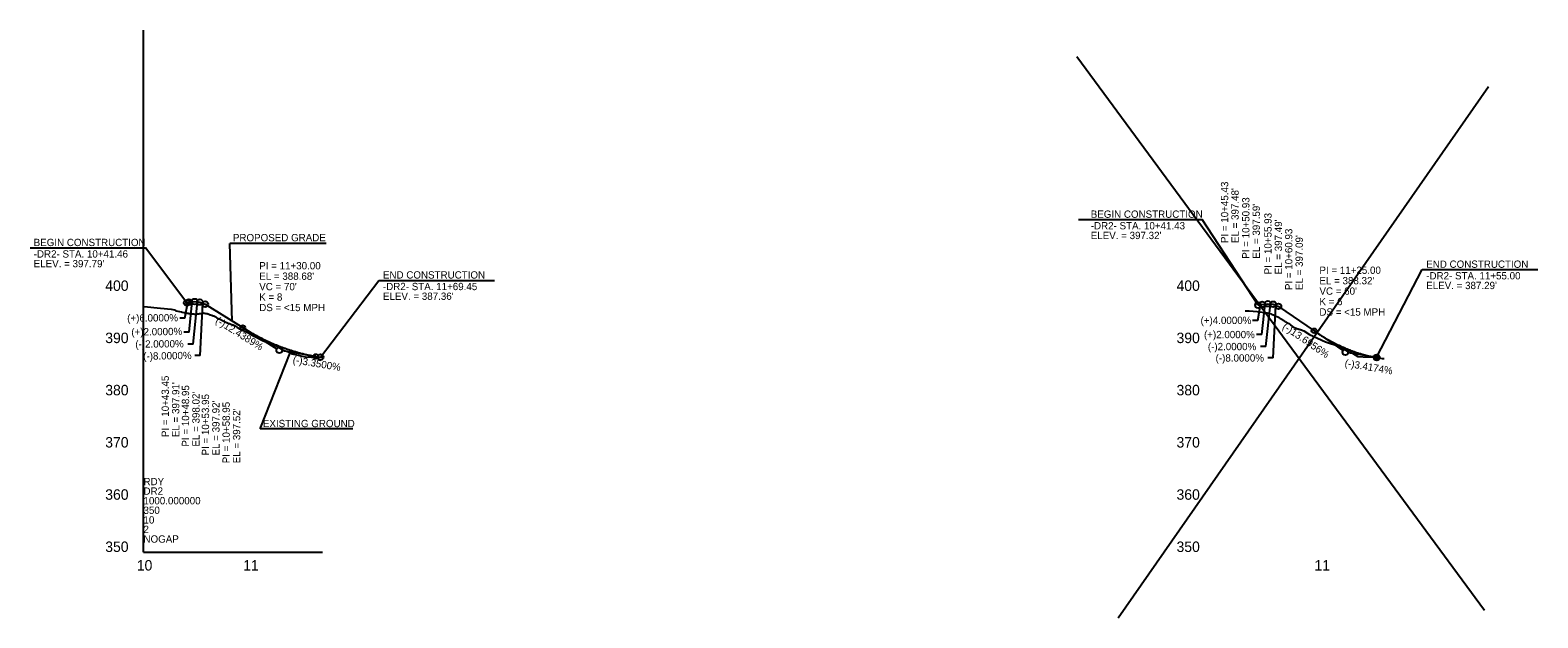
# Model space of a CAD drawing. Extents: x 1625686 to 1640492, y 1161393 to 1175642.
# Drawn here: x 1630096 to 1631539, y 1165841 to 1166403 of the extents above; entities that cross this region are included whole.
import ezdxf

# ---------------------------------------------------------------- set-up
doc = ezdxf.new("R2010")
doc.units = 0
for name, color, linetype in [('Exist Profile Cell', 7, 'Continuous'), ('Exist Vertical Profile Ground Line', 7, 'Continuous'), ('Exist Vertical Profile Horizontal Axis Label Major', 7, 'Continuous'), ('Exist Vertical Profile Vertical Axis Label', 7, 'Continuous'), ('Prop Vertical Profile Curve Label', 7, 'Continuous'), ('Prop Vertical Profile Grade', 7, 'Continuous'), ('Prop Vertical Profile Grade Label', 7, 'Continuous'), ('Prop VPI Label', 7, 'Continuous'), ('Scratch_Level_3', 7, 'Continuous')]:
    doc.layers.add(name, color=color, linetype=linetype)

msp = doc.modelspace()

# ---------------------------------------------------------------- linework, layer by layer
at = {"layer": 'Exist Profile Cell'}
for q in [(1630204.3, 1166403.4), (1630375.7, 1165903.4), (1630204.3, 1165903.4)]:
    msp.add_line((1630204.3, 1165903.4), q, dxfattribs=at)
at = {"layer": 'Exist Vertical Profile Ground Line'}
for points in [[(1630204.3, 1166138.9), (1630205, 1166138.9), (1630220.6, 1166137.2), (1630230.7, 1166136.2), (1630232.4, 1166135.8), (1630234.1, 1166135.5), (1630235.1, 1166134.5), (1630240.7, 1166133.6), (1630241.3, 1166133.3), (1630242.9, 1166133), (1630243.5, 1166132.9), (1630244.1, 1166132.8), (1630244.7, 1166132.7), (1630245.3, 1166132.6), (1630245.9, 1166132.5), (1630246.5, 1166132.4), (1630247.1, 1166132.3), (1630247.7, 1166132.2), (1630248.3, 1166132.1), (1630248.9, 1166132), (1630249.5, 1166132), (1630250.3, 1166131.9), (1630250.7, 1166131.8), (1630251.3, 1166131.7), (1630251.9, 1166131.7), (1630252.5, 1166131.6), (1630253.1, 1166131.5), (1630254, 1166131.5), (1630254.3, 1166131.5), (1630254.9, 1166131.5), (1630255.5, 1166131.6), (1630256.1, 1166131.6), (1630256.6, 1166131.7), (1630257.3, 1166131.8), (1630257.9, 1166131.9), (1630258.5, 1166132), (1630259.1, 1166132.1), (1630259.6, 1166132.2), (1630260.2, 1166132.3), (1630260.8, 1166132.4), (1630261.5, 1166132.6), (1630262, 1166132.5), (1630262.6, 1166132.4), (1630263.2, 1166132.3), (1630263.8, 1166132.2), (1630264.4, 1166132.1), (1630265.2, 1166132), (1630265.6, 1166131.8), (1630266.2, 1166131.6), (1630266.8, 1166131.4), (1630267.4, 1166131.2), (1630268, 1166130.9), (1630268.6, 1166130.7), (1630269.2, 1166130.5), (1630269.8, 1166130.3), (1630270.4, 1166130.1), (1630271, 1166129.9), (1630271.6, 1166129.7), (1630272.2, 1166129.5), (1630272.8, 1166129.2), (1630273.4, 1166128.8), (1630274, 1166128.4), (1630274.6, 1166128), (1630275.2, 1166127.7), (1630275.8, 1166127.4), (1630276.4, 1166127.1), (1630277, 1166126.8), (1630277.6, 1166126.5), (1630278.2, 1166126.2), (1630278.8, 1166125.9), (1630279.4, 1166125.6), (1630280, 1166125.3), (1630280.6, 1166125), (1630281.2, 1166124.7), (1630281.8, 1166124.4), (1630282.4, 1166124.1), (1630283, 1166123.8), (1630283.6, 1166123.5), (1630284.2, 1166123.3), (1630284.8, 1166123.1), (1630285.4, 1166122.8), (1630286, 1166122.6), (1630286.6, 1166122.4), (1630287.2, 1166122.2), (1630287.8, 1166121.9), (1630288.4, 1166121.7), (1630289, 1166121.5), (1630289.6, 1166121.3), (1630290.2, 1166121.1), (1630290.8, 1166120.9), (1630291.6, 1166120.6), (1630292, 1166120.3), (1630292.6, 1166119.9), (1630293.2, 1166119.5), (1630293.8, 1166119.1), (1630294.4, 1166118.7), (1630295, 1166118.3), (1630295.6, 1166117.8), (1630296.2, 1166117.4), (1630297, 1166116.9), (1630297.4, 1166116.7), (1630298, 1166116.5), (1630298.6, 1166116.2), (1630299.2, 1166116), (1630303.5, 1166114.2), (1630310, 1166110.4), (1630310.8, 1166110.1), (1630318.8, 1166106), (1630331.7, 1166101.1), (1630337.9, 1166097), (1630343, 1166095.4), (1630346.6, 1166093.3), (1630353.5, 1166091.8), (1630359.1, 1166090.6), (1630365.1, 1166090.2), (1630373.8, 1166090.2), (1630375.7, 1166089.9)], [(1631258.9, 1166134.6), (1631262.7, 1166134.7), (1631266.6, 1166134.3), (1631270.2, 1166134), (1631280, 1166132.6), (1631283.6, 1166131.6), (1631284, 1166131.4), (1631284.4, 1166131.2), (1631284.9, 1166131.1), (1631285.3, 1166130.9), (1631285.8, 1166130.7), (1631286.2, 1166130.5), (1631286.6, 1166130.3), (1631287.1, 1166130.1), (1631287.5, 1166129.9), (1631288, 1166129.7), (1631288.4, 1166129.5), (1631288.9, 1166129.3), (1631289.3, 1166129.1), (1631289.8, 1166128.9), (1631290.2, 1166128.7), (1631290.7, 1166128.5), (1631291.2, 1166128.3), (1631291.6, 1166128), (1631292, 1166127.7), (1631292.5, 1166127.4), (1631292.9, 1166127.1), (1631293.3, 1166126.8), (1631293.8, 1166126.5), (1631294.2, 1166126.2), (1631294.7, 1166125.9), (1631295.1, 1166125.6), (1631295.7, 1166125.2), (1631296, 1166125), (1631296.5, 1166124.8), (1631296.9, 1166124.5), (1631297.4, 1166124.3), (1631297.8, 1166124), (1631298.3, 1166123.7), (1631298.7, 1166123.5), (1631299.2, 1166123.2), (1631299.6, 1166123), (1631300.1, 1166122.7), (1631300.5, 1166122.5), (1631301.4, 1166121.9), (1631301.8, 1166121.6), (1631302.3, 1166121.2), (1631302.7, 1166120.8), (1631303.2, 1166120.5), (1631303.6, 1166120.1), (1631304.1, 1166119.8), (1631304.5, 1166119.4), (1631305, 1166119.1), (1631305.9, 1166118.5), (1631306.3, 1166118.3), (1631306.8, 1166118.2), (1631307.2, 1166118.1), (1631307.7, 1166117.9), (1631308.1, 1166117.8), (1631308.5, 1166117.6), (1631309, 1166117.5), (1631309.4, 1166117.4), (1631309.9, 1166117.2), (1631310.3, 1166117.1), (1631310.8, 1166116.9), (1631311.2, 1166116.8), (1631311.7, 1166116.7), (1631312.1, 1166116.5), (1631312.6, 1166116.4), (1631313, 1166116.3), (1631313.5, 1166116.1), (1631313.9, 1166115.9), (1631314.8, 1166115.5), (1631320.5, 1166111.8), (1631335.7, 1166105), (1631349.4, 1166100.3), (1631356.7, 1166096), (1631361.7, 1166094.2), (1631366.8, 1166091), (1631371.8, 1166090.5), (1631383.4, 1166090.1), (1631389.9, 1166089), (1631391.9, 1166088.8)]]:
    msp.add_lwpolyline(points, dxfattribs=at)
at = {"layer": 'Prop Vertical Profile Curve Label'}
for centre in [(1630299.3, 1166118.6), (1631324.7, 1166115.5), (1630369.3, 1166090.9), (1631384.7, 1166089.9)]:
    msp.add_circle(centre, 2.25, dxfattribs=at)
at = {"layer": 'Prop Vertical Profile Grade'}
for p, q in [((1630245.8, 1166142.4), (1630247.8, 1166142.9)), ((1630247.8, 1166142.9), (1630253.3, 1166143.5)), ((1630253.3, 1166143.5), (1630258.3, 1166143)), ((1630258.3, 1166143), (1630263.3, 1166141)), ((1630263.3, 1166141), (1630299.3, 1166118.6)), ((1631271.1, 1166140), (1631275.1, 1166140.8)), ((1631275.1, 1166140.8), (1631280.6, 1166141.4)), ((1631280.6, 1166141.4), (1631285.6, 1166140.9)), ((1631285.6, 1166140.9), (1631290.6, 1166138.9)), ((1631290.6, 1166138.9), (1631324.7, 1166115.5)), ((1630369.3, 1166090.9), (1630373.8, 1166090.2))]:
    msp.add_line(p, q, dxfattribs=at)
for points in [[(1630299.3, 1166118.6), (1630300.7, 1166117.7), (1630302.1, 1166116.9), (1630303.5, 1166116), (1630304.9, 1166115.2), (1630306.3, 1166114.4), (1630307.7, 1166113.6), (1630309.1, 1166112.8), (1630310.5, 1166112), (1630311.9, 1166111.3), (1630313.3, 1166110.5), (1630314.7, 1166109.8), (1630316.1, 1166109), (1630317.5, 1166108.3), (1630318.9, 1166107.6), (1630320.3, 1166106.9), (1630321.7, 1166106.3), (1630323.1, 1166105.6), (1630324.5, 1166105), (1630325.9, 1166104.3), (1630327.3, 1166103.7), (1630328.7, 1166103.1), (1630330.1, 1166102.5), (1630331.5, 1166101.9), (1630332.9, 1166101.3), (1630334.3, 1166100.8), (1630335.7, 1166100.2), (1630337.1, 1166099.7), (1630338.5, 1166099.2), (1630339.9, 1166098.7), (1630341.3, 1166098.2), (1630342.7, 1166097.7), (1630344.1, 1166097.2), (1630345.5, 1166096.8), (1630346.9, 1166096.3), (1630348.3, 1166095.9), (1630349.7, 1166095.5), (1630351.1, 1166095.1), (1630352.5, 1166094.7), (1630353.9, 1166094.3), (1630355.3, 1166093.9), (1630356.7, 1166093.6), (1630358.1, 1166093.2), (1630359.5, 1166092.9), (1630360.9, 1166092.6), (1630362.3, 1166092.3), (1630363.7, 1166092), (1630365.1, 1166091.7), (1630366.5, 1166091.4), (1630367.9, 1166091.2), (1630369.3, 1166090.9)], [(1631324.7, 1166115.5), (1631325.9, 1166114.7), (1631327.1, 1166113.9), (1631328.3, 1166113.1), (1631329.5, 1166112.3), (1631330.7, 1166111.6), (1631331.9, 1166110.8), (1631333.1, 1166110.1), (1631334.3, 1166109.3), (1631335.5, 1166108.6), (1631336.7, 1166107.9), (1631337.9, 1166107.2), (1631339.1, 1166106.5), (1631340.3, 1166105.9), (1631341.5, 1166105.2), (1631342.7, 1166104.6), (1631343.9, 1166104), (1631345.1, 1166103.3), (1631346.3, 1166102.7), (1631347.5, 1166102.1), (1631348.7, 1166101.6), (1631349.9, 1166101), (1631351.1, 1166100.4), (1631352.3, 1166099.9), (1631353.5, 1166099.4), (1631354.7, 1166098.8), (1631355.9, 1166098.3), (1631357.1, 1166097.8), (1631358.3, 1166097.3), (1631359.5, 1166096.9), (1631360.7, 1166096.4), (1631361.9, 1166096), (1631363.1, 1166095.5), (1631364.3, 1166095.1), (1631365.5, 1166094.7), (1631366.7, 1166094.3), (1631367.9, 1166093.9), (1631369.1, 1166093.6), (1631370.3, 1166093.2), (1631371.5, 1166092.9), (1631372.7, 1166092.5), (1631373.9, 1166092.2), (1631375.1, 1166091.9), (1631376.3, 1166091.6), (1631377.5, 1166091.3), (1631378.7, 1166091), (1631379.9, 1166090.8), (1631381.1, 1166090.5), (1631382.3, 1166090.3), (1631383.5, 1166090.1), (1631384.7, 1166089.9)]]:
    msp.add_spline(points, degree=3, dxfattribs=at)
at = {"layer": 'Prop Vertical Profile Grade Label'}
for p, q in [((1631099.2, 1166222), (1631217.8, 1166222)), ((1631271.1, 1166140), (1631217.8, 1166222)), ((1630289.3, 1166124.8), (1630287.1, 1166199)), ((1630379, 1166199), (1630287.1, 1166199)), ((1630095.8, 1166194.9), (1630206.1, 1166194.9)), ((1630245.8, 1166142.4), (1630206.1, 1166194.9)), ((1631384.6, 1166089.9), (1631428.3, 1166174.1)), ((1631428.3, 1166174.1), (1631539, 1166174.1)), ((1630373.8, 1166090.2), (1630429.7, 1166163.8)), ((1630429.7, 1166163.8), (1630540.3, 1166163.8)), ((1630244, 1166127.6), (1630246.8, 1166142.6)), ((1630247.9, 1166114.1), (1630251, 1166143.2)), ((1630251.7, 1166102.6), (1630256.1, 1166143.3)), ((1630258.6, 1166091.7), (1630261.2, 1166141.8)), ((1631270.8, 1166125.5), (1631273.6, 1166140.5)), ((1631274.8, 1166111.9), (1631277.9, 1166141.1)), ((1631278.5, 1166100.4), (1631282.9, 1166141.1)), ((1630244, 1166127.6), (1630239, 1166127.6)), ((1631285.5, 1166089.5), (1631288.1, 1166139.9)), ((1630247.9, 1166114.1), (1630242.9, 1166114.1)), ((1631270.8, 1166125.5), (1631265.8, 1166125.5)), ((1631274.8, 1166111.9), (1631269.8, 1166111.9)), ((1630251.7, 1166102.6), (1630246.7, 1166102.6)), ((1631278.5, 1166100.4), (1631273.5, 1166100.4)), ((1630258.6, 1166091.7), (1630253.6, 1166091.7)), ((1631285.5, 1166089.5), (1631280.5, 1166089.5))]:
    msp.add_line(p, q, dxfattribs=at)
at = {"layer": 'Prop VPI Label'}
for p, q in [((1630299.3, 1166118.6), (1630332, 1166098.3)), ((1631324.7, 1166115.5), (1631352.4, 1166096.5)), ((1630316.1, 1166021.7), (1630344.8, 1166094.4)), ((1630369.3, 1166090.9), (1630337, 1166096.4)), ((1631384.7, 1166089.9), (1631357.4, 1166094.5)), ((1630404.7, 1166021.7), (1630316.1, 1166021.7))]:
    msp.add_line(p, q, dxfattribs=at)
for centre in [(1630245.8, 1166142.4), (1630247.8, 1166142.9), (1630253.3, 1166143.5), (1630258.3, 1166143), (1630263.3, 1166141), (1631271.1, 1166140), (1631275.1, 1166140.8), (1631280.6, 1166141.4), (1631285.6, 1166140.9), (1631290.6, 1166138.9), (1630334.3, 1166096.8), (1631354.7, 1166095), (1630373.8, 1166090.2), (1631384.7, 1166089.9)]:
    msp.add_circle(centre, 2.75, dxfattribs=at)
at = {"layer": 'Scratch_Level_3'}
for p, q in [((1631097.7, 1166378.1), (1631488, 1165847.8)), ((1631137.1, 1165840.6), (1631491.6, 1166349.5))]:
    msp.add_line(p, q, dxfattribs=at)

# ---------------------------------------------------------------- texts
at = {"layer": 'Exist Profile Cell'}
for s, p in [('RDY', (1630204.3, 1165967.6)), ('1000.000000', (1630204.3, 1165949.3)), ('DR2', (1630204.3, 1165958.5)), ('350', (1630204.3, 1165940.1)), ('2', (1630204.3, 1165921.8)), ('10', (1630204.3, 1165930.9)), ('NOGAP', (1630204.3, 1165912.6))]:
    msp.add_text(s, height=7, dxfattribs=at).set_placement(p)
at = {"layer": 'Exist Vertical Profile Horizontal Axis Label Major'}
for s, p in [('10', (1630197.9, 1165885.9)), ('11', (1630299.7, 1165885.9)), ('11', (1631325.1, 1165885.9))]:
    msp.add_text(s, height=10, dxfattribs=at).set_placement(p)
at = {"layer": 'Exist Vertical Profile Vertical Axis Label'}
for s, p in [('400', (1630167.7, 1166153.7)), ('400', (1631193.1, 1166153.7)), ('390', (1630167.7, 1166103.7)), ('390', (1631193.1, 1166103.7)), ('380', (1630167.7, 1166053.7)), ('380', (1631193.1, 1166053.7)), ('370', (1630167.7, 1166003.7)), ('370', (1631193.1, 1166003.7)), ('360', (1630167.7, 1165953.7)), ('360', (1631193.1, 1165953.7)), ('350', (1630167.7, 1165903.7)), ('350', (1631193.1, 1165903.7))]:
    msp.add_text(s, height=10, dxfattribs=at).set_placement(p)
at = {"layer": 'Prop Vertical Profile Curve Label'}
for s, p in [("VC = 70'", (1630315.1, 1166154.3)), ("VC = 60'", (1631329.9, 1166150)), ('K = 8', (1630315.1, 1166144.3)), ('DS = <15 MPH', (1630315.1, 1166134.3)), ('K = 6', (1631329.9, 1166140)), ('DS = <15 MPH', (1631329.9, 1166130))]:
    msp.add_text(s, height=7, dxfattribs=at).set_placement(p)
at = {"layer": 'Prop Vertical Profile Grade Label'}
for s, p in [('PROPOSED GRADE', (1630289.9, 1166201.2)), ('(-)8.0000%', (1631230.5, 1166086))]:
    msp.add_text(s, height=7, dxfattribs=at).set_placement(p)
for s, rotation, p in [('(+)6.0000%', 0.4229, (1630188.7, 1166124.2)), ('(-)12.4389%', 328.1207, (1630272.5, 1166123.5)), ('(+)4.0000%', 360, (1631216.1, 1166122)), ('(+)2.0000%', 0.6388, (1630192.7, 1166110.9)), ('(+)2.0000%', 360, (1631219.4, 1166108.4)), ('(-)13.6956%', 325.5974, (1631293.8, 1166118)), ('(-)2.0000%', 0.4207, (1630196.5, 1166099.3)), ('(-)2.0000%', 360, (1631223.1, 1166096.9)), ('(-)8.0000%', 0.9396, (1630204.1, 1166087.7)), ('(-)3.3500%', 350.4912, (1630346.8, 1166084.6)), ('(-)3.4174%', 350.3035, (1631353.7, 1166081.4))]:
    msp.add_text(s, height=7, rotation=rotation, dxfattribs=at).set_placement(p)
at = {"layer": 'Prop VPI Label'}
for s, p in [('PI = 10+45.43', (1631242.6, 1166199.5)), ("EL = 397.48'", (1631252.6, 1166199.5)), ('PI = 10+50.93', (1631262.9, 1166184.5)), ("EL = 397.59'", (1631272.9, 1166184.5)), ('PI = 10+55.93', (1631284.1, 1166169.5)), ("EL = 397.49'", (1631294.1, 1166169.5)), ('PI = 10+60.93', (1631304, 1166154.5)), ("EL = 397.09'", (1631314, 1166154.5)), ('PI = 10+43.45', (1630228.6, 1166013.7)), ("EL = 397.91'", (1630238.6, 1166013.7)), ('PI = 10+48.95', (1630248, 1166004.6)), ("EL = 398.02'", (1630258, 1166004.6)), ('PI = 10+53.95', (1630267.1, 1165996.1)), ("EL = 397.92'", (1630277.1, 1165996.1)), ('PI = 10+58.95', (1630286.9, 1165988.6)), ("EL = 397.52'", (1630296.9, 1165988.6))]:
    msp.add_text(s, height=7, rotation=90, dxfattribs=at).set_placement(p)
for s, p in [('BEGIN CONSTRUCTION', (1631111, 1166223.7)), ('-DR2- STA. 10+41.43', (1631111, 1166212.6)), ('BEGIN CONSTRUCTION', (1630099.2, 1166196.6)), ("ELEV. = 397.32'", (1631111, 1166203.3)), ('-DR2- STA. 10+41.46', (1630099.2, 1166185.6)), ("ELEV. = 397.79'", (1630099.2, 1166176.3)), ('PI = 11+30.00', (1630315.1, 1166174.3)), ("EL = 388.68'", (1630315.1, 1166164.3)), ('END CONSTRUCTION', (1630433.5, 1166165.5)), ('PI = 11+25.00', (1631329.9, 1166170)), ('-DR2- STA. 11+55.00', (1631432.1, 1166164.7)), ('END CONSTRUCTION', (1631432.1, 1166175.8)), ('-DR2- STA. 11+69.45', (1630433.5, 1166154.4)), ("EL = 388.32'", (1631329.9, 1166160)), ("ELEV. = 387.29'", (1631432.1, 1166155.4)), ("ELEV. = 387.36'", (1630433.5, 1166145.1)), ('EXISTING GROUND', (1630318.6, 1166023.2))]:
    msp.add_text(s, height=7, dxfattribs=at).set_placement(p)

doc.saveas('drawing.dxf')
